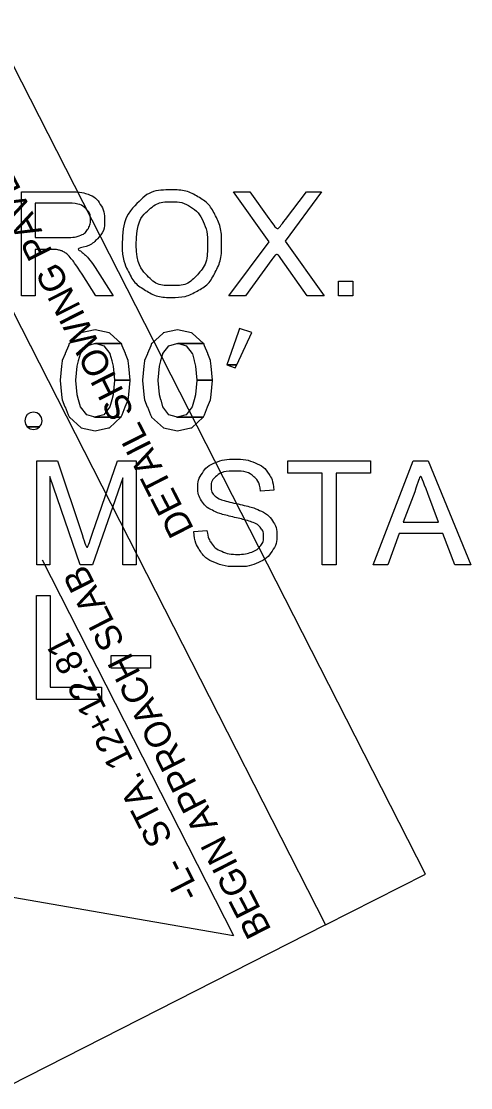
# Model space of a CAD drawing. Extents: x 557583 to 560285, y 513145 to 516544.
# Drawn here: x 558996.5 to 559082.9, y 515820.8 to 516025.9 of the extents above; entities that cross this region are included whole.
import ezdxf

# ---------------------------------------------------------------- set-up
doc = ezdxf.new("R2010")
doc.units = 0
for name, color, linetype in [('Default', 7, 'Continuous'), ('Prop DSN Text', 7, 'Continuous'), ('Scratch_Level_0', 7, 'Continuous')]:
    doc.layers.add(name, color=color, linetype=linetype)

msp = doc.modelspace()

# ---------------------------------------------------------------- linework, layer by layer
at = {"layer": 'Default'}
for points in [[(559036.4, 515973.13), (559044.13, 515983.5), (559037.31, 515993.13), (559040.45, 515993.13), (559044.11, 515988.01)], [(559047.3, 515987.81), (559051.31, 515993.13), (559054.19, 515993.13), (559047.24, 515983.63), (559054.74, 515973.13), (559051.48, 515973.13), (559046.42, 515980.27)], [(559044.64, 515980.07), (559039.58, 515973.13), (559036.4, 515973.13)], [(559064.14, 515921.36), (559071.82, 515941.36), (559074.69, 515941.36), (559082.86, 515921.36), (559079.84, 515921.36), (559077.53, 515927.41), (559069.14, 515927.41), (559066.94, 515921.36), (559064.14, 515921.36)], [(559045.04, 515935.74), (559042.51, 515935.54)], [(559072.11, 515935.44), (559069.9, 515929.56)], [(559069.9, 515929.56), (559076.69, 515929.56), (559074.6, 515935.12)], [(559029.7, 515927.8), (559032.2, 515928.01)]]:
    msp.add_lwpolyline(points, dxfattribs=at)
for points in [[(559008.06, 515947.71), (559010.72, 515947.17), (559013.31, 515947.71), (559013.46, 515947.74), (559015.66, 515949.77), (559010.67, 515949.77), (559010.54, 515949.8), (559010.48, 515949.82), (559009.09, 515950.22), (559007.92, 515951.73), (559007.92, 515951.74), (559007.92, 515951.74), (559007.55, 515953.08), (559007.54, 515953.11), (559007.28, 515954.08), (559007.26, 515954.14), (559007.02, 515956.83), (559007.02, 515956.87), (559007.03, 515956.9), (559007.26, 515959.59), (559007.54, 515960.61), (559007.54, 515960.64), (559007.9, 515961.95), (559007.91, 515961.99), (559009.09, 515963.51), (559010.59, 515963.91), (559010.64, 515963.92), (559010.78, 515963.96), (559015.71, 515963.96), (559013.53, 515965.95), (559013.42, 515965.97), (559010.75, 515966.56), (559010.74, 515966.56), (559007.97, 515965.97), (559007.94, 515965.95), (559005.79, 515963.96), (559005.75, 515963.92), (559005.74, 515963.91), (559005.58, 515963.51), (559004.95, 515961.99), (559004.93, 515961.95), (559004.39, 515960.64), (559004.39, 515960.61), (559004.28, 515959.59), (559004, 515956.9), (559003.99, 515956.87), (559004, 515956.83), (559004.27, 515954.14), (559004.27, 515954.08), (559004.37, 515953.11), (559004.38, 515953.08), (559004.92, 515951.74), (559004.93, 515951.73), (559005.55, 515950.22), (559005.71, 515949.82), (559005.72, 515949.8), (559005.76, 515949.77), (559008.02, 515947.74)], [(559014.2, 515959.59), (559014.42, 515956.9), (559017.45, 515956.9), (559017.18, 515959.59), (559017.09, 515960.61), (559017.07, 515960.64), (559017.07, 515960.64), (559016.55, 515961.95), (559016.54, 515961.95), (559016.53, 515961.99), (559015.92, 515963.51), (559015.91, 515963.51), (559015.76, 515963.91), (559015.75, 515963.92), (559015.71, 515963.96), (559010.78, 515963.96), (559010.91, 515963.92), (559010.95, 515963.91), (559012.37, 515963.51), (559013.54, 515961.99), (559013.57, 515961.95), (559013.92, 515960.64), (559013.92, 515960.61)], [(559010.81, 515949.8), (559010.67, 515949.77), (559015.66, 515949.77), (559015.7, 515949.8), (559015.72, 515949.82), (559015.88, 515950.22), (559016.51, 515951.73), (559016.51, 515951.74), (559017.07, 515953.08), (559017.08, 515953.11), (559017.17, 515954.08), (559017.18, 515954.14), (559017.45, 515956.83), (559017.45, 515956.87), (559017.45, 515956.9), (559014.42, 515956.9), (559014.42, 515956.87), (559014.41, 515956.83), (559014.2, 515954.14), (559014.19, 515954.08), (559013.93, 515953.11), (559013.92, 515953.08), (559013.56, 515951.74), (559013.55, 515951.73), (559012.37, 515950.22), (559010.88, 515949.82)]]:
    msp.add_lwpolyline(points, close=True, dxfattribs=at)
for points in [[(559044.11, 515988.01), (559045.25, 515986.42), (559045.72, 515985.55), (559046.38, 515986.63), (559047.3, 515987.81)], [(559046.42, 515980.27), (559045.99, 515980.88), (559045.59, 515981.5), (559044.94, 515980.47), (559044.64, 515980.07)], [(559032.2, 515928.01), (559032.38, 515926.51), (559033.03, 515925.54), (559033.68, 515924.58), (559035.04, 515923.98), (559036.41, 515923.39), (559038.12, 515923.39), (559039.63, 515923.39), (559040.79, 515923.84), (559041.95, 515924.29), (559042.52, 515925.08), (559043.09, 515925.86), (559043.09, 515926.79), (559043.09, 515927.73), (559042.54, 515928.44), (559042, 515929.14), (559040.74, 515929.62), (559039.93, 515929.93), (559037.16, 515930.59), (559034.39, 515931.26), (559033.29, 515931.84), (559031.86, 515932.59), (559031.15, 515933.71), (559030.45, 515934.82), (559030.45, 515936.2), (559030.45, 515937.71), (559031.31, 515939.03), (559032.17, 515940.35), (559033.83, 515941.03), (559035.48, 515941.71), (559037.51, 515941.71), (559039.73, 515941.71), (559041.44, 515941), (559043.14, 515940.28), (559044.05, 515938.89), (559044.97, 515937.5), (559045.04, 515935.74)], [(559042.51, 515935.54), (559042.3, 515937.44), (559041.12, 515938.41), (559039.93, 515939.38), (559037.62, 515939.38), (559035.2, 515939.38), (559034.1, 515938.5), (559033, 515937.62), (559033, 515936.38), (559033, 515935.3), (559033.78, 515934.6), (559034.55, 515933.91), (559037.79, 515933.17), (559041.03, 515932.44), (559042.23, 515931.9), (559043.97, 515931.09), (559044.8, 515929.86), (559045.63, 515928.62), (559045.63, 515927.02), (559045.63, 515925.42), (559044.72, 515924.01), (559043.8, 515922.6), (559042.09, 515921.81), (559040.38, 515921.03), (559038.24, 515921.03), (559035.52, 515921.03), (559033.68, 515921.82), (559031.85, 515922.61), (559030.8, 515924.2), (559029.76, 515925.79), (559029.7, 515927.8)], [(559074.6, 515935.12), (559073.66, 515937.65), (559073.19, 515939.26), (559072.79, 515937.34), (559072.11, 515935.44)]]:
    msp.add_open_spline(points, degree=3, dxfattribs=at)
at = {"layer": 'Prop DSN Text'}
for p in [(559000.51, 515922.31), (558938.73, 515867.27)]:
    msp.add_line(p, (559037.29, 515850.07), dxfattribs=at)
for points in [[(558879.66, 516196.55), (559055, 515852.15), (559074.16, 515861.9), (558898.81, 516206.31)], [(558879.66, 516196.55), (559055, 515852.15), (558908.44, 515777.53), (558733.09, 516121.93)]]:
    msp.add_lwpolyline(points, close=True, dxfattribs=at)
at = {"layer": 'Scratch_Level_0'}
for points in [[(558996.55, 515973.13), (558996.55, 515993.13), (559005.42, 515993.13)], [(559005.53, 515990.92), (558999.2, 515990.92), (558999.2, 515984.3)], [(558999.2, 515984.3), (559004.89, 515984.3)], [(559002.27, 515982.02), (558999.2, 515982.02), (558999.2, 515973.13), (558996.55, 515973.13)], [(559010.69, 515978.58), (559014.16, 515973.13), (559010.85, 515973.13), (559008.2, 515977.29)], [(559057.45, 515973.13), (559057.45, 515975.92), (559060.24, 515975.92), (559060.24, 515973.13), (559057.45, 515973.13)], [(558999.49, 515921.36), (558999.49, 515941.36), (559003.47, 515941.36), (559008.21, 515927.2)], [(559010.23, 515927.45), (559015.03, 515941.36), (559018.59, 515941.36), (559018.59, 515921.36), (559016.05, 515921.36), (559016.05, 515938.1), (559010.21, 515921.36), (559007.83, 515921.36), (559002.04, 515938.39), (559002.04, 515921.36), (558999.49, 515921.36)], [(559054.34, 515921.36), (559054.34, 515939), (559047.75, 515939), (559047.75, 515941.36), (559063.61, 515941.36), (559063.61, 515939), (559056.99, 515939), (559056.99, 515921.36), (559054.34, 515921.36)], [(558999.44, 515895.48), (558999.44, 515915.48), (559002.1, 515915.48), (559002.1, 515897.84), (559011.94, 515897.84), (559011.94, 515895.48), (558999.44, 515895.48)], [(559013.8, 515901.48), (559013.8, 515903.95), (559021.37, 515903.95), (559021.37, 515901.48), (559013.8, 515901.48)]]:
    msp.add_lwpolyline(points, dxfattribs=at)
for points in [[(559023.87, 515947.71), (559026.53, 515947.17), (559029.13, 515947.71), (559029.27, 515947.74), (559031.48, 515949.77), (559026.49, 515949.77), (559026.36, 515949.8), (559026.3, 515949.82), (559024.9, 515950.22), (559023.74, 515951.73), (559023.74, 515951.74), (559023.73, 515951.74), (559023.37, 515953.08), (559023.36, 515953.11), (559023.09, 515954.08), (559023.08, 515954.14), (559022.84, 515956.83), (559022.84, 515956.87), (559022.85, 515956.9), (559023.08, 515959.59), (559023.36, 515960.61), (559023.36, 515960.64), (559023.72, 515961.95), (559023.73, 515961.99), (559024.9, 515963.51), (559026.41, 515963.91), (559026.46, 515963.92), (559026.59, 515963.96), (559031.53, 515963.96), (559029.35, 515965.95), (559029.24, 515965.97), (559026.56, 515966.56), (559026.56, 515966.56), (559023.79, 515965.97), (559023.76, 515965.95), (559021.61, 515963.96), (559021.57, 515963.92), (559021.56, 515963.91), (559021.39, 515963.51), (559020.77, 515961.99), (559020.75, 515961.95), (559020.21, 515960.64), (559020.21, 515960.61), (559020.1, 515959.59), (559019.82, 515956.9), (559019.81, 515956.87), (559019.82, 515956.83), (559020.09, 515954.14), (559020.09, 515954.08), (559020.19, 515953.11), (559020.19, 515953.08), (559020.74, 515951.74), (559020.75, 515951.73), (559021.36, 515950.22), (559021.52, 515949.82), (559021.53, 515949.8), (559021.57, 515949.77), (559023.84, 515947.74)], [(559038.17, 515966.03), (559036.01, 515959.84), (559037.91, 515959.84), (559040.79, 515966.03), (559038.44, 515966.8)], [(559030.02, 515959.59), (559030.24, 515956.9), (559033.26, 515956.9), (559033, 515959.59), (559032.9, 515960.61), (559032.89, 515960.64), (559032.89, 515960.64), (559032.36, 515961.95), (559032.36, 515961.95), (559032.35, 515961.99), (559031.73, 515963.51), (559031.73, 515963.51), (559031.57, 515963.91), (559031.57, 515963.92), (559031.53, 515963.96), (559026.59, 515963.96), (559026.72, 515963.92), (559026.77, 515963.91), (559028.19, 515963.51), (559029.36, 515961.99), (559029.39, 515961.95), (559029.74, 515960.64), (559029.74, 515960.61)], [(559036.01, 515959.84), (559037.64, 515959.26), (559037.91, 515959.84)], [(559026.63, 515949.8), (559026.49, 515949.77), (559031.48, 515949.77), (559031.52, 515949.8), (559031.54, 515949.82), (559031.7, 515950.22), (559032.32, 515951.73), (559032.33, 515951.74), (559032.89, 515953.08), (559032.9, 515953.11), (559032.99, 515954.08), (559033, 515954.14), (559033.26, 515956.83), (559033.27, 515956.87), (559033.26, 515956.9), (559030.23, 515956.9), (559030.23, 515956.87), (559030.23, 515956.83), (559030.02, 515954.14), (559030.01, 515954.08), (559029.75, 515953.11), (559029.74, 515953.08), (559029.38, 515951.74), (559029.37, 515951.73), (559028.19, 515950.22), (559026.7, 515949.82)], [(558997.31, 515948.44), (558997.67, 515947.9), (559000.04, 515947.9), (559000.4, 515948.44), (559000.53, 515949.08), (559000.4, 515949.72), (559000.04, 515950.26), (558999.5, 515950.62), (558998.86, 515950.74), (558998.21, 515950.62), (558997.67, 515950.26), (558997.31, 515949.72), (558997.18, 515949.08)], [(558998.21, 515947.53), (558998.86, 515947.41), (558999.5, 515947.53), (559000.04, 515947.9), (558997.67, 515947.9)]]:
    msp.add_lwpolyline(points, close=True, dxfattribs=at)
for points in [[(559005.42, 515993.13), (559008.09, 515993.13), (559009.48, 515992.59), (559010.88, 515992.05), (559011.71, 515990.69), (559012.54, 515989.33), (559012.54, 515987.67), (559012.54, 515985.55), (559011.16, 515984.09), (559009.78, 515982.63), (559006.91, 515982.23), (559007.96, 515981.73), (559008.5, 515981.24), (559009.66, 515980.17), (559010.69, 515978.58)], [(559015.89, 515982.87), (559015.89, 515987.85), (559018.57, 515990.67), (559021.24, 515993.48), (559025.47, 515993.48), (559028.24, 515993.48), (559030.47, 515992.16), (559032.69, 515990.84), (559033.86, 515988.47), (559035.02, 515986.1), (559035.02, 515983.1), (559035.02, 515980.06), (559033.8, 515977.66), (559032.57, 515975.26), (559030.32, 515974.03), (559028.06, 515972.8), (559025.46, 515972.8), (559022.63, 515972.8), (559020.41, 515974.16), (559018.19, 515975.52), (559017.04, 515977.88), (559015.89, 515980.24), (559015.89, 515982.87)], [(559004.89, 515984.3), (559006.7, 515984.3), (559007.72, 515984.68), (559008.75, 515985.06), (559009.28, 515985.88), (559009.81, 515986.71), (559009.81, 515987.67), (559009.81, 515989.09), (559008.78, 515990.01), (559007.75, 515990.92), (559005.53, 515990.92)], [(559018.62, 515982.84), (559018.62, 515979.23), (559020.57, 515977.15), (559022.51, 515975.07), (559025.45, 515975.07), (559028.43, 515975.07), (559030.36, 515977.17), (559032.3, 515979.27), (559032.3, 515983.13), (559032.3, 515985.57), (559031.47, 515987.39), (559030.64, 515989.21), (559029.05, 515990.21), (559027.46, 515991.21), (559025.49, 515991.21), (559022.67, 515991.21), (559020.65, 515989.28), (559018.62, 515987.35), (559018.62, 515982.84)], [(559008.2, 515977.29), (559007.04, 515979.09), (559006.29, 515980.05), (559005.54, 515981), (559004.95, 515981.39), (559004.36, 515981.77), (559003.74, 515981.92), (559003.29, 515982.02), (559002.27, 515982.02)], [(559008.21, 515927.2), (559008.86, 515925.22), (559009.16, 515924.24), (559009.51, 515925.33), (559010.23, 515927.45)]]:
    msp.add_open_spline(points, degree=3, dxfattribs=at)

# ---------------------------------------------------------------- texts
at = {"layer": 'Prop DSN Text'}
for s, p in [('DETAIL SHOWING PAVEMENT TO BRIDGE RELATIONSHIP', (559029.79, 515928.27)), ('BEGIN APPROACH SLAB', (559044.67, 515851.17)), ('-L-  STA. 12+12.81', (559031.12, 515858.15))]:
    msp.add_text(s, height=5, rotation=116.9819, dxfattribs=at).set_placement(p)

doc.saveas('drawing.dxf')
